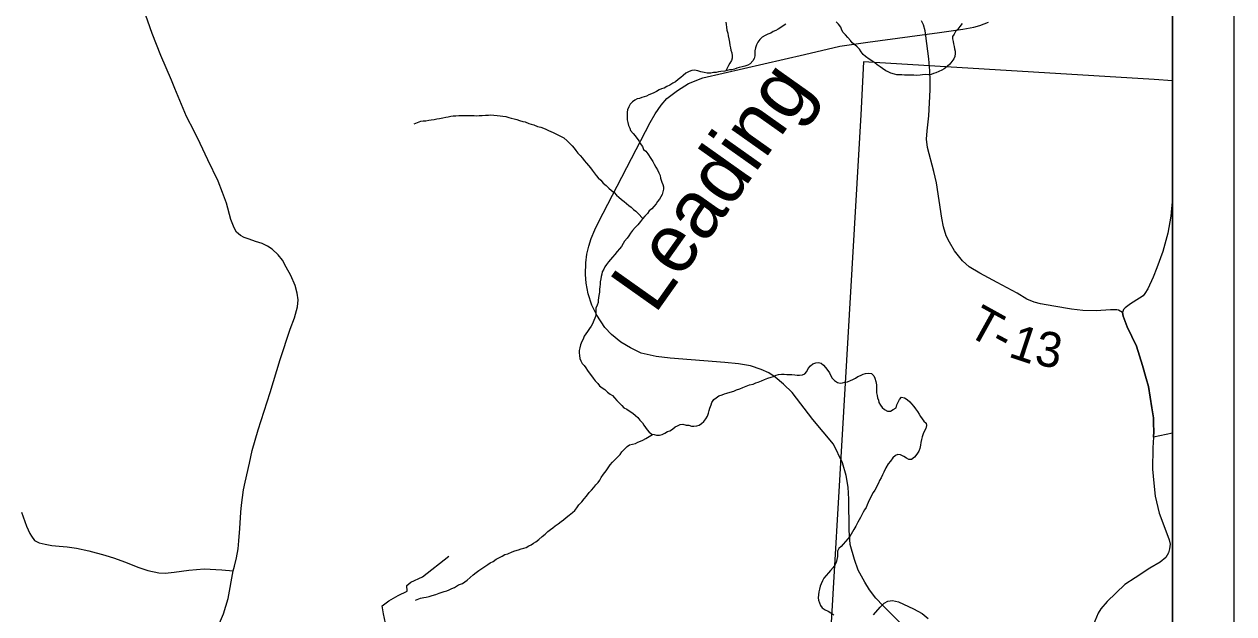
# Model space of a CAD drawing. Extents: x -13.7 to 34, y 0 to 32.3.
# Drawn here: x 28.447 to 30.417, y 15.91 to 16.87 of the extents above; entities that cross this region are included whole.
import ezdxf

# ---------------------------------------------------------------- set-up
doc = ezdxf.new("R2010")
doc.units = 0
for name, color, linetype in [('GM_X_Corporation', 7, 'Continuous'), ('GM_X_County_Road', 7, 'Continuous'), ('GM_X_Minor_River', 7, 'Continuous'), ('GM_X_Minor_River_Text', 7, 'Continuous'), ('GM_X_Rail_Line', 7, 'Continuous'), ('GM_X_Township_Road', 7, 'Continuous'), ('GM_X_Township_Road_Text', 7, 'Continuous'), ('SH_Data', 7, 'Continuous')]:
    doc.layers.add(name, color=color, linetype=linetype)

msp = doc.modelspace()

# ---------------------------------------------------------------- linework, layer by layer
at = {"layer": 'GM_X_Corporation'}
for points in [[(25.5491, 14.1), (30.3167, 14.1), (30.3167, 20.877), (30.2775, 20.8796), (29.9598, 20.9), (26.0026, 20.9)], [(27.6886, 14.8962), (28.6553, 14.8354), (29.7019, 14.7755), (30.3167, 14.7354), (30.3167, 20.877), (30.2775, 20.8796), (29.9598, 20.9), (26.0026, 20.9)]]:
    msp.add_lwpolyline(points, dxfattribs=at)
msp.add_lwpolyline([(30.3167, 15.7567), (30.3167, 16.7776), (30.2872, 16.7795), (29.8135, 16.8087), (29.8095, 16.7223), (29.7836, 16.2855), (29.7549, 15.7939)], close=True, dxfattribs=at)
at = {"layer": 'GM_X_County_Road'}
for points in [[(28.7869, 15.9798), (28.789, 15.9875), (28.7923, 16.001), (28.7951, 16.0159), (28.796, 16.0285), (28.7977, 16.0488), (28.7995, 16.0757), (28.8005, 16.0866), (28.804, 16.1118), (28.8065, 16.1244), (28.8135, 16.155), (28.8181, 16.176), (28.8276, 16.2092), (28.8471, 16.2701), (28.8636, 16.324), (28.88, 16.3735), (28.887, 16.392), (28.892, 16.4099), (28.8931, 16.4212), (28.8915, 16.4317), (28.888, 16.4443), (28.881, 16.4608), (28.8733, 16.4744), (28.8672, 16.4858), (28.8602, 16.4945), (28.8504, 16.5038), (28.8429, 16.5087), (28.8341, 16.5126), (28.8234, 16.5162), (28.8128, 16.5196), (28.8049, 16.5223), (28.7988, 16.5257), (28.7925, 16.5311), (28.7885, 16.5381), (28.7834, 16.5519), (28.776, 16.5783), (28.7696, 16.5957), (28.7624, 16.614), (28.7456, 16.649), (28.7333, 16.6756), (28.7236, 16.6954), (28.7111, 16.7195), (28.6919, 16.765), (28.6863, 16.7785), (28.6693, 16.8186), (28.6553, 16.8546), (28.641, 16.8947)], [(30.3167, 16.5855), (30.3154, 16.5696), (30.314, 16.5574), (30.3092, 16.5294), (30.3012, 16.5), (30.2915, 16.473), (30.2854, 16.4579), (30.2769, 16.4388), (30.2718, 16.4316), (30.2689, 16.4274), (30.2633, 16.4238), (30.2486, 16.4144), (30.2399, 16.4082), (30.237, 16.4052), (30.2354, 16.4006)], [(30.2354, 16.4006), (30.2364, 16.3943), (30.2428, 16.3773), (30.258, 16.3454), (30.268, 16.314), (30.2742, 16.2929), (30.2779, 16.2801), (30.2831, 16.2454), (30.2857, 16.2291), (30.2858, 16.2196), (30.2865, 16.2067), (30.286, 16.1976)], [(30.286, 16.1976), (30.2847, 16.18), (30.284, 16.1453), (30.2864, 16.1225), (30.2888, 16.1013), (30.2951, 16.0738), (30.3076, 16.0408), (30.3114, 16.0306), (30.3128, 16.0234), (30.3119, 16.016), (30.3103, 16.0093), (30.3057, 16.0016), (30.2967, 15.994), (30.2801, 15.984), (30.2559, 15.9688), (30.239, 15.9576), (30.2103, 15.9301), (30.2002, 15.9179), (30.196, 15.9111), (30.1903, 15.8978), (30.1716, 15.8333), (30.168, 15.8093), (30.1652, 15.7975)], [(28.4421, 16.0757), (28.4505, 16.0525), (28.4556, 16.0406), (28.4583, 16.0364), (28.4636, 16.0295), (28.4709, 16.0257), (28.4807, 16.0231), (28.4916, 16.0213), (28.5036, 16.0203), (28.5166, 16.019), (28.5318, 16.0169), (28.5518, 16.0124), (28.5782, 16.0057), (28.5936, 16.0003), (28.6098, 15.9945), (28.6335, 15.9854), (28.6481, 15.9803), (28.6662, 15.9769), (28.6761, 15.9763), (28.6907, 15.9776), (28.7146, 15.9809), (28.7396, 15.9832), (28.7683, 15.9818), (28.7869, 15.9798)], [(28.751, 15.861), (28.763, 15.8911), (28.7712, 15.91), (28.7786, 15.9349), (28.7869, 15.9798)], [(29.8297, 15.9081), (29.8409, 15.921), (29.8475, 15.9274), (29.8533, 15.9308), (29.8608, 15.9319), (29.8706, 15.9297), (29.8952, 15.918), (29.9089, 15.9105), (29.9188, 15.9025)]]:
    msp.add_lwpolyline(points, dxfattribs=at)
at = {"layer": 'GM_X_Minor_River'}
for points in [[(29.5895, 16.8731), (29.5899, 16.8693), (29.5907, 16.8647), (29.5911, 16.8598), (29.5926, 16.8552), (29.5934, 16.8507), (29.5942, 16.8461), (29.5953, 16.8405), (29.5961, 16.8355), (29.5969, 16.8314), (29.5976, 16.8276), (29.5992, 16.8234), (29.5996, 16.8185), (29.5999, 16.8147), (29.5988, 16.8109), (29.5958, 16.8063), (29.5939, 16.8025), (29.5892, 16.7937)], [(29.6871, 16.8699), (29.683, 16.8669), (29.6792, 16.8646), (29.6746, 16.8615), (29.6708, 16.8596), (29.6667, 16.8577), (29.6625, 16.855), (29.6576, 16.8535)], [(29.9742, 16.871), (29.9704, 16.8661), (29.967, 16.8619), (29.9636, 16.8581), (29.961, 16.8535), (29.9587, 16.8497), (29.9587, 16.8459), (29.9595, 16.8414), (29.9602, 16.8376), (29.961, 16.8334), (29.9618, 16.8296), (29.9626, 16.8258), (29.963, 16.822), (29.9622, 16.8171), (29.9607, 16.8133), (29.9573, 16.8091), (29.9543, 16.8049), (29.9497, 16.8011), (29.9448, 16.7969), (29.941, 16.795), (29.9361, 16.7927), (29.9315, 16.7908), (29.9277, 16.7897), (29.9239, 16.7878), (29.9198, 16.7874), (29.9148, 16.7878), (29.9095, 16.7874), (29.9057, 16.787), (29.9004, 16.7862), (29.8958, 16.7866), (29.8901, 16.7866), (29.8863, 16.7869), (29.8806, 16.7869), (29.8761, 16.7873), (29.8723, 16.7873), (29.8681, 16.7876), (29.8643, 16.7884), (29.8582, 16.7899), (29.8537, 16.7922), (29.8499, 16.794), (29.8445, 16.7974), (29.8407, 16.8005), (29.8358, 16.8039), (29.832, 16.8069), (29.8274, 16.8099), (29.8229, 16.8126), (29.8171, 16.8171), (29.8133, 16.8205), (29.8099, 16.8247), (29.8069, 16.8292), (29.8031, 16.833), (29.7989, 16.8368), (29.7951, 16.8394), (29.7924, 16.8432), (29.7882, 16.8481), (29.784, 16.8523), (29.7806, 16.8565), (29.7783, 16.8603), (29.7764, 16.8652), (29.773, 16.8697), (29.7691, 16.8735)], [(29.6576, 16.8535), (29.6534, 16.8516), (29.6488, 16.8489), (29.6447, 16.8448), (29.6416, 16.8406), (29.6394, 16.836), (29.6379, 16.8315), (29.6367, 16.8265), (29.6368, 16.8227), (29.6364, 16.8185), (29.6353, 16.814), (29.6334, 16.8102), (29.6288, 16.8053), (29.625, 16.8033), (29.6205, 16.8014), (29.6159, 16.8003), (29.611, 16.7991), (29.6072, 16.798), (29.6034, 16.7968), (29.5992, 16.7957), (29.5954, 16.7953), (29.5913, 16.7942), (29.5875, 16.7934), (29.5814, 16.793), (29.5776, 16.7922), (29.5734, 16.7911), (29.5692, 16.7911), (29.5647, 16.7903), (29.559, 16.7899), (29.5541, 16.791), (29.5487, 16.7922), (29.5438, 16.7937), (29.5381, 16.7948), (29.5339, 16.7944), (29.5294, 16.7929), (29.5241, 16.7902), (29.5199, 16.7864), (29.5161, 16.783), (29.5116, 16.7799), (29.5074, 16.7757), (29.5032, 16.7738), (29.4979, 16.7704), (29.4934, 16.7681), (29.4888, 16.7658), (29.4846, 16.7643), (29.4808, 16.7631), (29.4763, 16.7601), (29.4721, 16.7582), (29.4683, 16.7563), (29.4642, 16.7548), (29.46, 16.7528), (29.4562, 16.7517), (29.4524, 16.7506), (29.4486, 16.749), (29.4448, 16.7483), (29.441, 16.7463), (29.4372, 16.7433), (29.4338, 16.7395), (29.4312, 16.7353), (29.4293, 16.7304), (29.4285, 16.7266), (29.4289, 16.722), (29.4286, 16.7182), (29.4286, 16.7141), (29.4297, 16.7095), (29.4309, 16.705), (29.4328, 16.7008), (29.4343, 16.697), (29.4385, 16.6921), (29.4419, 16.6883), (29.4446, 16.6841), (29.448, 16.6792), (29.4499, 16.6754), (29.4534, 16.6705), (29.4553, 16.6656), (29.4591, 16.6633), (29.4621, 16.6587), (29.4671, 16.6512), (29.4705, 16.6462), (29.4724, 16.6421), (29.4755, 16.6368), (29.4782, 16.6326), (29.4801, 16.6277), (29.4824, 16.6235), (29.4831, 16.619), (29.4854, 16.6129), (29.4866, 16.6091), (29.4877, 16.6053), (29.4877, 16.6011), (29.487, 16.597), (29.4855, 16.5928), (29.4836, 16.589), (29.4813, 16.5852), (29.4783, 16.581), (29.4757, 16.5772), (29.4719, 16.573), (29.4688, 16.5692), (29.4647, 16.5658), (29.4617, 16.5616), (29.4575, 16.5571), (29.4537, 16.5529)], [(29.0819, 16.7075), (29.0925, 16.7121), (29.0967, 16.7125), (29.1009, 16.7125), (29.1054, 16.7133), (29.1096, 16.714), (29.1142, 16.7148), (29.1187, 16.7156), (29.1233, 16.7163), (29.1282, 16.7171), (29.1335, 16.7186), (29.1373, 16.719), (29.1415, 16.7198), (29.1453, 16.7206), (29.1498, 16.7206), (29.1544, 16.721), (29.1586, 16.721), (29.1643, 16.7214), (29.1688, 16.721), (29.1749, 16.721), (29.1795, 16.721), (29.1836, 16.7207), (29.1878, 16.7214), (29.1927, 16.7214), (29.1981, 16.7215), (29.2026, 16.7215), (29.2068, 16.7222), (29.2113, 16.7219), (29.2167, 16.7211), (29.222, 16.7204), (29.2262, 16.72), (29.2311, 16.7193), (29.2357, 16.7181), (29.2395, 16.717), (29.2448, 16.7155), (29.249, 16.7144), (29.2535, 16.7129), (29.2588, 16.7114), (29.2626, 16.7106), (29.2683, 16.7084), (29.2725, 16.7072), (29.2767, 16.7057), (29.2828, 16.7035), (29.2881, 16.7019), (29.2923, 16.7004), (29.2961, 16.6989), (29.3007, 16.6967), (29.3045, 16.6952), (29.3083, 16.6937), (29.3124, 16.6914), (29.317, 16.6891), (29.3212, 16.6872), (29.3254, 16.6846), (29.3307, 16.68), (29.3353, 16.6755), (29.3391, 16.6717), (29.3421, 16.6679), (29.3452, 16.6641), (29.3486, 16.66), (29.3524, 16.6558), (29.3562, 16.6517), (29.3585, 16.6479), (29.3623, 16.6437), (29.3657, 16.6395), (29.3688, 16.6358), (29.3715, 16.632), (29.3749, 16.6278), (29.3783, 16.6236), (29.3817, 16.6195), (29.3856, 16.6161), (29.3897, 16.6111), (29.3943, 16.607), (29.3989, 16.6028), (29.4034, 16.599), (29.4073, 16.5956), (29.4111, 16.5915), (29.4152, 16.5884), (29.4194, 16.5843), (29.4236, 16.5809), (29.4274, 16.5778), (29.4312, 16.5748), (29.435, 16.5722), (29.4392, 16.568), (29.443, 16.5654), (29.4465, 16.5616), (29.4544, 16.5537)], [(29.4537, 16.5529), (29.4503, 16.5487), (29.4461, 16.5434), (29.4416, 16.5388), (29.4374, 16.5342), (29.434, 16.5297), (29.4314, 16.5255), (29.4287, 16.5217), (29.4242, 16.5167), (29.4219, 16.5129), (29.4193, 16.508), (29.4162, 16.5042), (29.4125, 16.4996), (29.4087, 16.4951), (29.4049, 16.4905), (29.4015, 16.4867), (29.3981, 16.4829), (29.395, 16.4787), (29.3924, 16.4749), (29.3905, 16.4711), (29.3882, 16.4669), (29.3875, 16.4628), (29.3864, 16.459), (29.386, 16.4552), (29.3849, 16.4506), (29.3845, 16.4465), (29.3841, 16.4423), (29.3838, 16.4385), (29.3838, 16.4335), (29.3827, 16.4282), (29.3819, 16.4244), (29.3812, 16.4206), (29.3812, 16.4168), (29.38, 16.4123), (29.3778, 16.4074), (29.3778, 16.4036), (29.3778, 16.3998), (29.3774, 16.3956), (29.3759, 16.3914), (29.3744, 16.3872), (29.3721, 16.3819), (29.3703, 16.3781), (29.3676, 16.3743), (29.3642, 16.3698), (29.3616, 16.366), (29.3589, 16.3618), (29.357, 16.3572), (29.3548, 16.353), (29.3525, 16.3477), (29.3514, 16.3432), (29.3506, 16.3386), (29.3506, 16.3348), (29.351, 16.3306), (29.3518, 16.3257), (29.3533, 16.3219), (29.3556, 16.3177), (29.3587, 16.314), (29.3613, 16.3102), (29.364, 16.306), (29.367, 16.3022), (29.3705, 16.2973), (29.3731, 16.2935), (29.3766, 16.2893), (29.3808, 16.2848), (29.3838, 16.281), (29.388, 16.278), (29.3922, 16.275), (29.3968, 16.2708), (29.4009, 16.2674), (29.4047, 16.2655), (29.4078, 16.2617), (29.4116, 16.2572), (29.4162, 16.2526), (29.42, 16.2492), (29.4234, 16.2454), (29.428, 16.2432), (29.4322, 16.2402), (29.4379, 16.2364), (29.4424, 16.233), (29.4462, 16.2296), (29.4493, 16.2254), (29.4538, 16.2209), (29.4558, 16.2171), (29.4584, 16.2133), (29.4611, 16.2095), (29.4645, 16.2057), (29.4687, 16.2023), (29.4725, 16.2016), (29.4767, 16.2008), (29.4816, 16.2008), (29.4858, 16.202), (29.49, 16.2043), (29.4941, 16.2065), (29.4979, 16.2081), (29.5025, 16.2104), (29.507, 16.2142), (29.5108, 16.2161), (29.515, 16.218), (29.5196, 16.2187), (29.5249, 16.2172), (29.529, 16.2169)], [(29.529, 16.2169), (29.5332, 16.2154), (29.537, 16.2154), (29.542, 16.2158), (29.5461, 16.2173), (29.5499, 16.22), (29.5537, 16.223), (29.5567, 16.2276), (29.5594, 16.2317), (29.5609, 16.2367), (29.5624, 16.2409), (29.5635, 16.245), (29.5654, 16.2504), (29.5665, 16.2542), (29.5696, 16.2587), (29.5737, 16.2618), (29.5779, 16.2648), (29.5832, 16.2667), (29.587, 16.2682), (29.5912, 16.269), (29.5965, 16.2709), (29.6022, 16.2725), (29.6067, 16.2747), (29.6124, 16.2763), (29.617, 16.2782), (29.6227, 16.2805), (29.628, 16.2828), (29.6337, 16.2839), (29.6382, 16.2862), (29.642, 16.287), (29.6477, 16.2893), (29.6526, 16.2912), (29.6576, 16.2935), (29.6633, 16.295), (29.6671, 16.2965), (29.6716, 16.2984), (29.6754, 16.2996), (29.68, 16.3003), (29.6845, 16.3), (29.6887, 16.2996), (29.6925, 16.2996), (29.6967, 16.2993), (29.7016, 16.2989), (29.7058, 16.2985), (29.7096, 16.2985), (29.7141, 16.2989), (29.7183, 16.3008), (29.7213, 16.3046), (29.7236, 16.3092), (29.727, 16.3134), (29.7312, 16.3168), (29.7361, 16.3187), (29.7403, 16.3191), (29.7448, 16.318), (29.7486, 16.3149), (29.7517, 16.3108), (29.7555, 16.3059), (29.7582, 16.3021), (29.7605, 16.2975), (29.7628, 16.2937), (29.7666, 16.2896), (29.7715, 16.2865), (29.7757, 16.2854), (29.7795, 16.2858), (29.7833, 16.2869), (29.7875, 16.2877), (29.7924, 16.2896), (29.7962, 16.2915), (29.8003, 16.2938), (29.8045, 16.2961), (29.8087, 16.298), (29.8129, 16.2999), (29.817, 16.3014), (29.822, 16.3015), (29.8265, 16.3011), (29.8303, 16.2973), (29.8322, 16.2935), (29.8338, 16.2882), (29.8346, 16.2825), (29.8346, 16.2787), (29.8346, 16.2746), (29.835, 16.2696), (29.8357, 16.2655), (29.8365, 16.2613), (29.838, 16.2575), (29.8388, 16.2537), (29.8411, 16.2495), (29.8438, 16.2457), (29.848, 16.2423), (29.8525, 16.2401), (29.8575, 16.2397), (29.862, 16.2424), (29.8666, 16.2454), (29.8681, 16.25), (29.8703, 16.2545), (29.8722, 16.2591), (29.8756, 16.2629), (29.8802, 16.2618), (29.8847, 16.2591), (29.8889, 16.2553), (29.892, 16.2516)], [(29.892, 16.2516), (29.8954, 16.2474), (29.8985, 16.2436), (29.9015, 16.2394), (29.9042, 16.2349), (29.9065, 16.2311), (29.9091, 16.2273), (29.9118, 16.2235), (29.9156, 16.2205), (29.916, 16.2163), (29.9153, 16.2114), (29.9122, 16.2068), (29.9107, 16.2027), (29.9092, 16.1981), (29.9081, 16.1935), (29.907, 16.189), (29.9062, 16.1844), (29.9055, 16.1791), (29.9036, 16.1746), (29.9006, 16.1696), (29.8964, 16.1651), (29.8918, 16.1612), (29.8873, 16.1609), (29.8835, 16.1635), (29.8793, 16.1658), (29.874, 16.1688), (29.8694, 16.1695), (29.8656, 16.1676), (29.8611, 16.1638), (29.8573, 16.1585), (29.8535, 16.1539), (29.8501, 16.1475), (29.8467, 16.1406), (29.8445, 16.1361), (29.8426, 16.1311), (29.8399, 16.127), (29.838, 16.1228), (29.8361, 16.119), (29.8343, 16.1152), (29.832, 16.111), (29.8293, 16.1072), (29.8271, 16.1034), (29.8248, 16.0985), (29.8229, 16.0947), (29.821, 16.0909), (29.8195, 16.0871), (29.818, 16.0829), (29.8154, 16.0791), (29.8131, 16.0753), (29.8108, 16.0711), (29.8089, 16.0666), (29.8067, 16.0628), (29.8044, 16.059), (29.801, 16.0529), (29.7976, 16.0472), (29.7935, 16.0396), (29.7912, 16.0358), (29.7882, 16.032), (29.7844, 16.0278), (29.7806, 16.0236), (29.7772, 16.0194), (29.7734, 16.0164), (29.7715, 16.0118), (29.7711, 16.0073), (29.7711, 16.0031), (29.7704, 15.9985), (29.7693, 15.9936), (29.767, 15.9894), (29.7644, 15.9852), (29.7598, 15.9807), (29.7564, 15.9765), (29.753, 15.9723), (29.7492, 15.9681), (29.747, 15.9636), (29.7447, 15.959), (29.7432, 15.9552), (29.7421, 15.9503), (29.7409, 15.9457), (29.7402, 15.9408), (29.7398, 15.9362), (29.7402, 15.9324), (29.7417, 15.9279), (29.7436, 15.9237), (29.7463, 15.9196), (29.7513, 15.9165), (29.7562, 15.9143), (29.7604, 15.9116), (29.7653, 15.9082)], [(29.0841, 15.9323), (29.092, 15.9354), (29.0973, 15.9365), (29.1011, 15.9373), (29.1064, 15.9384), (29.1113, 15.9396), (29.117, 15.9415), (29.1223, 15.9434), (29.1307, 15.9461), (29.1349, 15.9476), (29.139, 15.9492), (29.1432, 15.9514), (29.1474, 15.953), (29.1538, 15.9572), (29.1603, 15.9595), (29.1644, 15.9621), (29.1682, 15.9648), (29.1728, 15.969), (29.1777, 15.9732), (29.183, 15.9773), (29.1872, 15.9804), (29.1921, 15.9838), (29.1966, 15.9872), (29.2016, 15.9903), (29.2054, 15.993), (29.2103, 15.9952), (29.2152, 15.9987), (29.2198, 16.001), (29.2251, 16.0036), (29.2296, 16.0063), (29.2342, 16.0078), (29.2414, 16.0109), (29.2459, 16.0124), (29.2516, 16.0143), (29.2562, 16.0158), (29.2604, 16.0166), (29.2642, 16.0181), (29.2683, 16.0208), (29.2721, 16.0223), (29.2759, 16.025), (29.2797, 16.0269), (29.2846, 16.0307), (29.2903, 16.0357), (29.2949, 16.0395), (29.2994, 16.044), (29.3036, 16.0471), (29.3077, 16.0497), (29.3115, 16.0532), (29.3161, 16.0566), (29.321, 16.06), (29.3252, 16.0631), (29.3293, 16.0665), (29.3343, 16.0703), (29.3396, 16.0749), (29.3434, 16.0783), (29.3468, 16.0825), (29.3498, 16.0874), (29.3547, 16.0924), (29.3585, 16.0973), (29.3623, 16.1015), (29.3668, 16.1072), (29.3706, 16.1114), (29.3744, 16.1156), (29.3778, 16.1197), (29.3812, 16.1235), (29.3842, 16.1273), (29.3865, 16.1319), (29.3899, 16.1372), (29.3944, 16.1429), (29.3975, 16.1475), (29.4009, 16.1524), (29.4047, 16.1566), (29.4092, 16.1612), (29.4134, 16.1657), (29.4175, 16.1695), (29.4202, 16.1737), (29.4247, 16.1787), (29.4285, 16.1825), (29.4327, 16.1848), (29.4372, 16.1863), (29.4422, 16.1874), (29.4463, 16.1893), (29.4505, 16.1909), (29.4543, 16.1924), (29.4589, 16.1951), (29.4697, 16.2021)]]:
    msp.add_lwpolyline(points, dxfattribs=at)
at = {"layer": 'GM_X_Rail_Line'}
msp.add_lwpolyline([(29.9289, 15.8404), (29.8454, 15.9232), (29.8338, 15.9356), (29.8234, 15.9488), (29.8156, 15.9614), (29.8051, 15.981), (29.7987, 15.9986), (29.7916, 16.023), (29.79, 16.0462), (29.7897, 16.0967), (29.7887, 16.1161), (29.7851, 16.135), (29.7793, 16.1556), (29.7647, 16.186), (29.7311, 16.2261), (29.6974, 16.27), (29.6834, 16.284), (29.6696, 16.2951), (29.6594, 16.3023), (29.6467, 16.3078), (29.6298, 16.3134), (29.6102, 16.3171), (29.5878, 16.3192), (29.4985, 16.3261), (29.4759, 16.3287), (29.4514, 16.3343), (29.4341, 16.3427), (29.4183, 16.3519), (29.4032, 16.3647), (29.3925, 16.3763), (29.3793, 16.3959), (29.3709, 16.4126), (29.3651, 16.4311), (29.3618, 16.4482), (29.3606, 16.4622), (29.3613, 16.4811), (29.3631, 16.4955), (29.366, 16.5082), (29.37, 16.5209), (29.3758, 16.5349), (29.3818, 16.5474), (29.4661, 16.7096), (29.4745, 16.724), (29.4841, 16.7382), (29.4935, 16.7487), (29.5104, 16.7621), (29.5284, 16.7732), (29.5518, 16.7823), (29.7175, 16.8206), (29.7751, 16.8341), (29.8205, 16.8404), (29.9373, 16.8562), (29.9751, 16.8615), (29.9935, 16.865), (30.0031, 16.8675), (30.0173, 16.8729)], dxfattribs=at)
at = {"layer": 'GM_X_Township_Road'}
for points in [[(30.2354, 16.4006), (30.229, 16.404), (30.2261, 16.4049), (30.2161, 16.4047), (30.1924, 16.4034), (30.1709, 16.4036), (30.1521, 16.4058), (30.1234, 16.411), (30.1019, 16.4144), (30.0913, 16.4171), (30.0798, 16.4223), (30.0637, 16.4318), (30.0312, 16.4492), (30.0032, 16.4644), (29.9858, 16.4746), (29.9749, 16.4844), (29.9617, 16.5009), (29.9535, 16.5149), (29.9484, 16.5254), (29.9437, 16.5401), (29.9413, 16.554), (29.9326, 16.6118), (29.9281, 16.6298), (29.9179, 16.669), (29.9161, 16.6825), (29.917, 16.696), (29.92, 16.7205), (29.922, 16.7628), (29.9222, 16.7784), (29.9215, 16.7939), (29.9198, 16.8134), (29.915, 16.8507), (29.9139, 16.8588), (29.9115, 16.869), (29.9083, 16.8755)], [(30.286, 16.1976), (30.2865, 16.2067), (30.2858, 16.2196), (30.2857, 16.2291), (30.2831, 16.2454), (30.2779, 16.2801), (30.2742, 16.2929), (30.268, 16.314), (30.258, 16.3454), (30.2428, 16.3773), (30.2364, 16.3943), (30.2354, 16.4006)], [(30.3167, 16.2038), (30.2964, 16.1996), (30.286, 16.1976)], [(29.0862, 15.8371), (29.0934, 15.849), (29.0944, 15.8562), (29.0895, 15.8635), (29.0766, 15.8716), (29.0589, 15.8828), (29.0421, 15.8889), (29.0351, 15.8949), (29.0318, 15.9099), (29.0299, 15.9232), (29.0404, 15.9309), (29.0556, 15.9396), (29.0706, 15.947), (29.0701, 15.9562), (29.0766, 15.9615), (29.0953, 15.9702), (29.138, 16.004)]]:
    msp.add_lwpolyline(points, dxfattribs=at)
at = {"layer": 'SH_Data'}
for points in [[(23.4167, 21), (30.4167, 21), (30.4167, 14), (23.4167, 14)], [(23.5167, 20.9), (30.3167, 20.9), (30.3167, 14.1), (23.5167, 14.1)]]:
    msp.add_lwpolyline(points, close=True, dxfattribs=at)

# ---------------------------------------------------------------- texts
at = {"layer": 'GM_X_Minor_River_Text'}
msp.add_text('Leading', height=0.0947, rotation=54.6919, dxfattribs=at).set_placement((29.4738, 16.3961))
at = {"layer": 'GM_X_Township_Road_Text'}
for s, rotation, p in [('T', 331.0078, (29.9793, 16.3653)), ('1', 341.6345, (30.0476, 16.3291)), ('-', 331.9053, (30.0173, 16.3442)), ('3', 351.0208, (30.0906, 16.3157))]:
    msp.add_text(s, height=0.0568, rotation=rotation, dxfattribs=at).set_placement(p)

doc.saveas('drawing.dxf')
